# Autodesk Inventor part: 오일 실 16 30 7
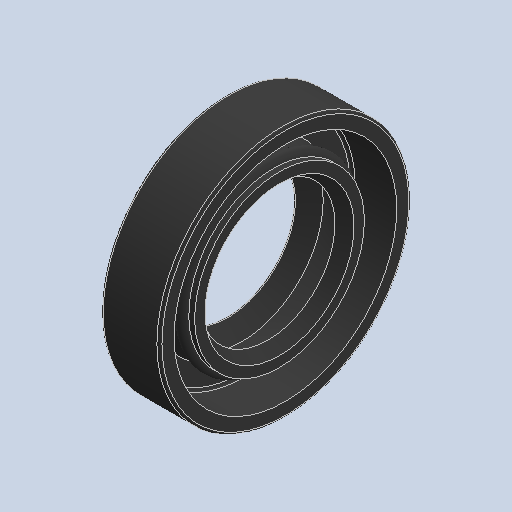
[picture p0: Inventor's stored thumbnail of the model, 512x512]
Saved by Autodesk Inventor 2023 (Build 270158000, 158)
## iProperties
Created: 2025-10
Part Number: 오일 실 16 30 7
Material: 고무
Description: 오일-실
Document SubType Name: Modeling
Designer: home
Density: 0.93 g/cm^3
Appearance: 기본값
Author: jhkim
Sending System: Autodesk Inventor 2026
Preprocessor: ST-DEVELOPER v20.1
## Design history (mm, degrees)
feature "Solid1"
node "솔리드1"
